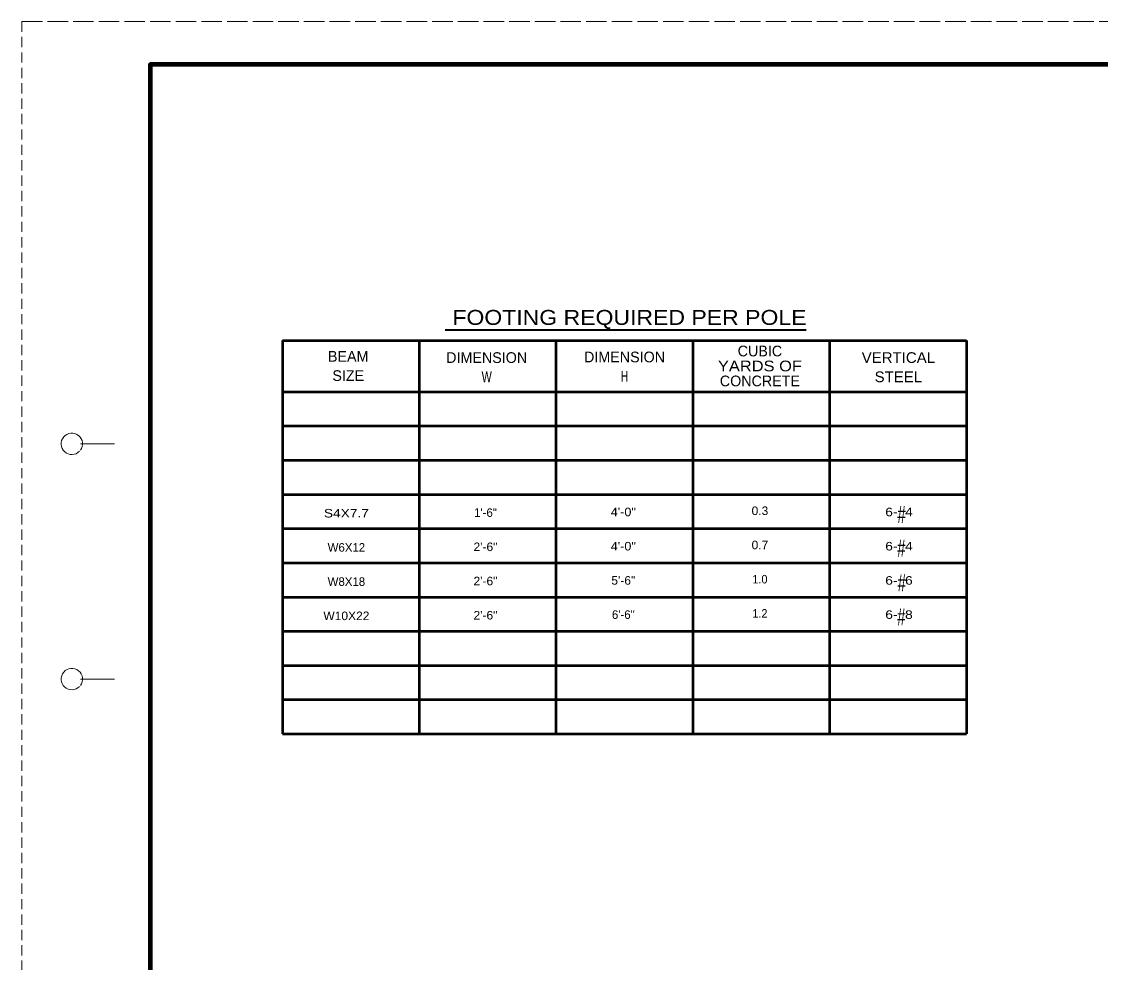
# Model space of a CAD drawing. Extents: x -2 to 678, y -1 to 439.
# Drawn here: x -2 to 250.4, y 219.3 to 439.3 of the extents above; entities that cross this region are included whole.
import ezdxf
from ezdxf.enums import TextEntityAlignment as Align

# ---------------------------------------------------------------- set-up
doc = ezdxf.new("R2010")
doc.units = 0
doc.header["$LTSCALE"] = 0.8
doc.linetypes.add('LONG_DASHED', pattern=[7.5, 6, -1.5])
doc.linetypes.add('MEDIUM_DASHED', pattern=[4.5, 3, -1.5])
doc.layers.add('1', color=7, linetype='Continuous', lineweight=35)
doc.layers.add('61', color=7, linetype='Continuous', lineweight=35)

msp = doc.modelspace()

# ---------------------------------------------------------------- linework, layer by layer
at = {"layer": '1', "linetype": 'MEDIUM_DASHED', "lineweight": 13}
msp.add_line((-1.9245, 439.3337), (-1.9845, -0.7063), dxfattribs=at)
at = {"layer": '1', "lineweight": 40}
msp.add_line((97.0711, 367.2528), (181.5817, 367.2528), dxfattribs=at)
at = {"layer": '1', "lineweight": 53}
for p, q in [((59.0167, 364.7638), (219.0168, 364.7638)), ((59.0167, 364.7638), (59.0167, 272.7638)), ((91.0168, 364.7638), (91.0168, 272.7638)), ((123.0168, 364.7638), (123.0168, 272.7638)), ((155.0168, 364.7638), (155.0168, 272.7638)), ((187.0168, 364.7638), (187.0168, 272.7638)), ((219.0168, 364.7638), (219.0168, 272.7638)), ((59.0167, 352.7638), (219.0168, 352.7638)), ((59.0167, 344.7638), (219.0168, 344.7638)), ((59.0167, 336.7638), (219.0168, 336.7638)), ((59.0167, 328.7638), (219.0168, 328.7638)), ((59.0167, 320.7638), (219.0168, 320.7638)), ((59.0167, 312.7638), (219.0168, 312.7638)), ((59.0167, 304.7638), (219.0168, 304.7638)), ((59.0167, 296.7638), (219.0168, 296.7638)), ((59.0167, 288.7638), (219.0168, 288.7638)), ((59.0167, 280.7638), (219.0168, 280.7638)), ((59.0167, 272.7638), (219.0168, 272.7638))]:
    msp.add_line(p, q, dxfattribs=at)
at = {"layer": '61', "linetype": 'LONG_DASHED', "lineweight": 13}
msp.add_line((-1.9245, 439.3337), (678.0955, 439.3337), dxfattribs=at)
at = {"layer": '61', "lineweight": 13}
for p, q in [((11.7955, 340.5737), (19.7755, 340.5937)), ((11.7755, 285.5737), (19.7755, 285.5737))]:
    msp.add_line(p, q, dxfattribs=at)
at = {"layer": '61', "lineweight": 158}
msp.add_lwpolyline([(667.1155, 429.3337), (28.0755, 429.3337), (28.0755, 9.3137)], dxfattribs=at)
at = {"layer": '61', "lineweight": 13}
for centre, end in [((9.7733, 340.575), 316.23216), ((9.7733, 285.575), 315.37577)]:
    msp.add_arc(centre, 2.5, 323.13009, end, dxfattribs=at)

# ---------------------------------------------------------------- texts
at = {"layer": '1'}
for s, height, width, p in [('FOOTING REQUIRED PER POLE', 3.5, 1.15, (98.7908, 368.3997)), ('#', 4, 0.65, (202.8906, 322.1004)), ('#', 4, 0.65, (202.8387, 314.2096)), ('#', 4, 0.65, (202.9425, 306.0592)), ('#', 4, 0.65, (202.8387, 298.1683))]:
    msp.add_text(s, height=height, dxfattribs=dict(at, width=width)).set_placement(p)
for s, height, p in [('CUBIC', 2.5, (170.732, 361.0448)), ('BEAM', 2.5, (74.4282, 359.7948)), ('DIMENSION', 2.5, (106.8161, 359.5082)), ('DIMENSION', 2.5, (139.0607, 359.6515)), ('SIZE', 2.5, (74.4283, 355.2948)), ('CONCRETE', 2.5, (170.732, 354.0448)), ('1\'-6"', 2, (106.5295, 323.5049)), ('W6X12', 2, (73.9983, 315.3616)), ('W8X18', 2, (73.9984, 307.3616)), ('6\'-6"', 2, (138.7741, 299.6482))]:
    msp.add_text(s, height=height, dxfattribs=at).set_placement(p, align=Align.CENTER)
for s, height, width, p in [('VERTICAL', 2.5, 1.05, (203.1199, 359.5082)), ('YARDS OF', 2.5, 1.15, (170.732, 357.5448)), ('W', 2.5, 0.75, (106.8162, 355.0082)), ('H', 2.5, 0.7, (139.0608, 355.1515)), ('STEEL', 2.5, 1.05, (203.12, 355.0082)), ('4\'-0"', 2, 1.1, (138.7741, 323.6482)), ('0.3', 2, 1.05, (170.7321, 323.935)), ('6-  4', 2, 1.2, (203.2632, 323.6482)), ('S4X7.7', 2, 1.2, (73.9984, 323.3616)), ('2\'-6"', 2, 1.05, (106.5295, 315.5049)), ('4\'-0"', 2, 1.1, (138.7741, 315.6482)), ('0.7', 2, 1.05, (170.7321, 315.935)), ('6-  4', 2, 1.2, (203.2632, 315.6482)), ('2\'-6"', 2, 1.05, (106.5295, 307.5049)), ('5\'-6"', 2, 1.05, (138.7741, 307.6482)), ('1.0', 2, 0.95, (170.7321, 307.935)), ('6-  6', 2, 1.2, (203.2632, 307.6482)), ('W10X22', 2, 1.05, (73.9983, 299.3616)), ('2\'-6"', 2, 1.05, (106.5295, 299.5049)), ('1.2', 2, 0.95, (170.732, 299.935)), ('6-  8', 2, 1.2, (203.2632, 299.6482))]:
    msp.add_text(s, height=height, dxfattribs=dict(at, width=width)).set_placement(p, align=Align.CENTER)

doc.saveas('drawing.dxf')
